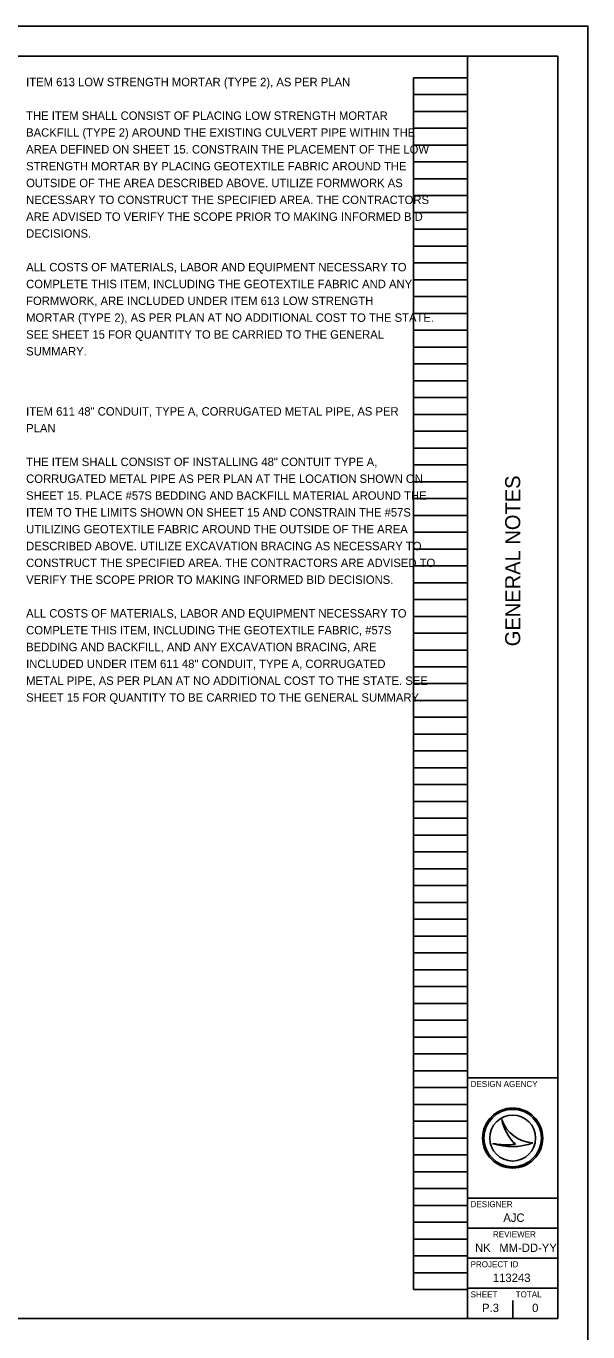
# Model space of a CAD drawing. Extents: x -8.9 to 34, y -10.9 to 22.
# Drawn here: x 24.66 to 34, y 0.28 to 22 of the extents above; entities that cross this region are included whole.
import ezdxf

# ---------------------------------------------------------------- set-up
doc = ezdxf.new("R2010")
doc.units = 0
for name, color, linetype in [('RD_P_Text', 7, 'Continuous'), ('SH_Border', 7, 'Continuous'), ('SH_Cut_Line', 7, 'Continuous'), ('SH_Data', 7, 'Continuous'), ('SH_Text', 7, 'Continuous')]:
    doc.layers.add(name, color=color, linetype=linetype)

msp = doc.modelspace()

# ---------------------------------------------------------------- linework, layer by layer
at = {"layer": 'SH_Border'}
for p, q in [((32, 0.5), (32, 21.5)), ((32, 4.5), (33.5, 4.5)), ((32, 2.5), (33.5, 2.5)), ((32, 2), (33.5, 2)), ((32, 1.5), (33.5, 1.5)), ((32, 1), (33.5, 1))]:
    msp.add_line(p, q, dxfattribs=at)
msp.add_lwpolyline([(1.5, 21.5), (33.5, 21.5), (33.5, 0.5), (1.5, 0.5)], close=True, dxfattribs=at)
at = {"layer": 'SH_Cut_Line'}
msp.add_lwpolyline([(0, 0), (34, 0), (34, 22), (0, 22)], close=True, dxfattribs=at)
at = {"layer": 'SH_Data'}
for p, q in [((31.1, 0.98), (31.1, 21.14)), ((31.1, 21.14), (32, 21.14)), ((32, 0.98), (32, 21.14)), ((31.1, 20.86), (32, 20.86)), ((31.1, 20.58), (32, 20.58)), ((31.1, 20.3), (32, 20.3)), ((31.1, 20.02), (32, 20.02)), ((31.1, 19.74), (32, 19.74)), ((31.1, 19.46), (32, 19.46)), ((31.1, 19.18), (32, 19.18)), ((31.1, 18.9), (32, 18.9)), ((31.1, 18.62), (32, 18.62)), ((31.1, 18.34), (32, 18.34)), ((31.1, 18.06), (32, 18.06)), ((31.1, 17.78), (32, 17.78)), ((31.1, 17.5), (32, 17.5)), ((31.1, 17.22), (32, 17.22)), ((31.1, 16.94), (32, 16.94)), ((31.1, 16.66), (32, 16.66)), ((31.1, 16.38), (32, 16.38)), ((31.1, 16.1), (32, 16.1)), ((31.1, 15.82), (32, 15.82)), ((31.1, 15.54), (32, 15.54)), ((31.1, 15.26), (32, 15.26)), ((31.1, 14.98), (32, 14.98)), ((31.1, 14.7), (32, 14.7)), ((31.1, 14.42), (32, 14.42)), ((31.1, 14.14), (32, 14.14)), ((31.1, 13.86), (32, 13.86)), ((31.1, 13.58), (32, 13.58)), ((31.1, 13.3), (32, 13.3)), ((31.1, 13.02), (32, 13.02)), ((31.1, 12.74), (32, 12.74)), ((31.1, 12.46), (32, 12.46)), ((31.1, 12.18), (32, 12.18)), ((31.1, 11.9), (32, 11.9)), ((31.1, 11.62), (32, 11.62)), ((31.1, 11.34), (32, 11.34)), ((31.1, 11.06), (32, 11.06)), ((31.1, 10.78), (32, 10.78)), ((31.1, 10.5), (32, 10.5)), ((31.1, 10.22), (32, 10.22)), ((31.1, 9.94), (32, 9.94)), ((31.1, 9.66), (32, 9.66)), ((31.1, 9.38), (32, 9.38)), ((31.1, 9.1), (32, 9.1)), ((31.1, 8.82), (32, 8.82)), ((31.1, 8.54), (32, 8.54)), ((31.1, 8.26), (32, 8.26)), ((31.1, 7.98), (32, 7.98)), ((31.1, 7.7), (32, 7.7)), ((31.1, 7.42), (32, 7.42)), ((31.1, 7.14), (32, 7.14)), ((31.1, 6.86), (32, 6.86)), ((31.1, 6.58), (32, 6.58)), ((31.1, 6.3), (32, 6.3)), ((31.1, 6.02), (32, 6.02)), ((31.1, 5.74), (32, 5.74)), ((31.1, 5.46), (32, 5.46)), ((31.1, 5.18), (32, 5.18)), ((31.1, 4.9), (32, 4.9)), ((31.1, 4.62), (32, 4.62)), ((31.1, 4.34), (32, 4.34)), ((31.1, 4.06), (32, 4.06)), ((31.1, 3.78), (32, 3.78)), ((32.567, 3.81), (32.567, 3.81)), ((31.1, 3.5), (32, 3.5)), ((32.75, 3.5), (32.75, 3.5)), ((32.417, 3.41), (32.417, 3.41)), ((33.087, 3.419), (33.087, 3.419)), ((31.1, 3.22), (32, 3.22)), ((31.1, 2.94), (32, 2.94)), ((31.1, 2.66), (32, 2.66)), ((31.1, 2.38), (32, 2.38)), ((31.1, 2.1), (32, 2.1)), ((31.1, 1.82), (32, 1.82)), ((31.1, 1.54), (32, 1.54)), ((31.1, 1.26), (32, 1.26)), ((31.1, 0.98), (32, 0.98)), ((32.375, 0.675), (32.375, 0.675)), ((32.75, 0.5), (32.75, 0.8))]:
    msp.add_line(p, q, dxfattribs=at)
for radius in [0.5, 0.477, 0.477, 0.382]:
    msp.add_circle((32.75, 3.5), radius, dxfattribs=at)
for centre, radius, start, end in [((33.116, 3.998), 0.58, 198.9257, 198.9319), ((33.347, 3.97), 0.796, 191.6379, 191.6421), ((33.116, 3.998), 0.58, 198.9319, 267.1657), ((33.347, 3.97), 0.796, 191.6421, 226.0947), ((32.739, 4.37), 1.013, 251.4576, 290.0832), ((32.648, 4.654), 1.266, 259.4964, 259.4995), ((32.739, 4.37), 1.013, 251.4527, 251.4576), ((32.648, 4.654), 1.266, 259.4995, 276.6672)]:
    msp.add_arc(centre, radius, start, end, dxfattribs=at)

# ---------------------------------------------------------------- texts
at = {"layer": 'RD_P_Text'}
for s, p in [('ITEM 613 LOW STRENGTH MORTAR (TYPE 2), AS PER PLAN', (24.66, 21)), ('ITEM 611 48" CONDUIT, TYPE A, CORRUGATED METAL PIPE, AS PER ', (24.66, 15.52)), ('PLAN', (24.66, 15.24))]:
    msp.add_text(s, height=0.14, dxfattribs=at).set_placement(p)
at = {"layer": 'SH_Data'}
msp.add_text('GENERAL NOTES', height=0.25, rotation=90, dxfattribs=at).set_placement((32.875, 11.682))
for s, height, p in [('DESIGN AGENCY', 0.1, (32.05, 4.35)), ('DESIGNER', 0.1, (32.05, 2.35)), ('AJC', 0.14, (32.594, 2.105)), ('NK', 0.14, (32.124, 1.605)), ('REVIEWER', 0.1, (32.422, 1.85)), ('MM-DD-YY', 0.14, (32.527, 1.605)), ('PROJECT ID', 0.1, (32.05, 1.35)), ('113243', 0.14, (32.421, 1.105)), ('SHEET', 0.1, (32.05, 0.85)), ('TOTAL', 0.1, (32.8, 0.85)), ('P.3', 0.14, (32.241, 0.605)), ('0', 0.14, (33.073, 0.605))]:
    msp.add_text(s, height=height, dxfattribs=at).set_placement(p)
at = {"layer": 'SH_Text'}
for s, p in [('THE ITEM SHALL CONSIST OF PLACING LOW STRENGTH MORTAR ', (24.66, 20.44)), ('BACKFILL (TYPE 2) AROUND THE EXISTING CULVERT PIPE WITHIN THE ', (24.66, 20.16)), ('AREA DEFINED ON SHEET 15. CONSTRAIN THE PLACEMENT OF THE LOW ', (24.66, 19.88)), ('STRENGTH MORTAR BY PLACING GEOTEXTILE FABRIC AROUND THE ', (24.66, 19.6)), ('OUTSIDE OF THE AREA DESCRIBED ABOVE. UTILIZE FORMWORK AS ', (24.66, 19.32)), ('NECESSARY TO CONSTRUCT THE SPECIFIED AREA. THE CONTRACTORS ', (24.66, 19.04)), ('ARE ADVISED TO VERIFY THE SCOPE PRIOR TO MAKING INFORMED BID ', (24.66, 18.76)), ('DECISIONS.', (24.66, 18.48)), ('ALL COSTS OF MATERIALS, LABOR AND EQUIPMENT NECESSARY TO ', (24.66, 17.92)), ('COMPLETE THIS ITEM, INCLUDING THE GEOTEXTILE FABRIC AND ANY ', (24.66, 17.64)), ('FORMWORK, ARE INCLUDED UNDER ITEM 613 LOW STRENGTH ', (24.66, 17.36)), ('MORTAR (TYPE 2), AS PER PLAN AT NO ADDITIONAL COST TO THE STATE. ', (24.66, 17.08)), ('SEE SHEET 15 FOR QUANTITY TO BE CARRIED TO THE GENERAL ', (24.66, 16.8)), ('SUMMARY.', (24.66, 16.52)), ('THE ITEM SHALL CONSIST OF INSTALLING 48" CONTUIT TYPE A, ', (24.66, 14.68)), ('CORRUGATED METAL PIPE AS PER PLAN AT THE LOCATION SHOWN ON ', (24.66, 14.4)), ('SHEET 15. PLACE #57S BEDDING AND BACKFILL MATERIAL AROUND THE ', (24.66, 14.12)), ('ITEM TO THE LIMITS SHOWN ON SHEET 15 AND CONSTRAIN THE #57S ', (24.66, 13.84)), ('UTILIZING GEOTEXTILE FABRIC AROUND THE OUTSIDE OF THE AREA ', (24.66, 13.56)), ('DESCRIBED ABOVE. UTILIZE EXCAVATION BRACING AS NECESSARY TO ', (24.66, 13.28)), ('CONSTRUCT THE SPECIFIED AREA. THE CONTRACTORS ARE ADVISED TO ', (24.66, 13)), ('VERIFY THE SCOPE PRIOR TO MAKING INFORMED BID DECISIONS.', (24.66, 12.72)), ('ALL COSTS OF MATERIALS, LABOR AND EQUIPMENT NECESSARY TO ', (24.66, 12.16)), ('COMPLETE THIS ITEM, INCLUDING THE GEOTEXTILE FABRIC, #57S ', (24.66, 11.88)), ('BEDDING AND BACKFILL, AND ANY EXCAVATION BRACING, ARE ', (24.66, 11.6)), ('INCLUDED UNDER ITEM 611 48" CONDUIT, TYPE A, CORRUGATED ', (24.66, 11.32)), ('METAL PIPE, AS PER PLAN AT NO ADDITIONAL COST TO THE STATE. SEE ', (24.66, 11.04)), ('SHEET 15 FOR QUANTITY TO BE CARRIED TO THE GENERAL SUMMARY.', (24.66, 10.76))]:
    msp.add_text(s, height=0.14, dxfattribs=at).set_placement(p)

doc.saveas('drawing.dxf')
